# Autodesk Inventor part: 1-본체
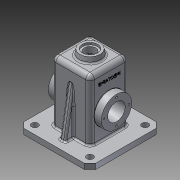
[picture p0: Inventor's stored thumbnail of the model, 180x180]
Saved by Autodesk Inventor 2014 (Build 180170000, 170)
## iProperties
Created: 2016-02
Part Number: 1-본체
Material: 알루미늄 6061
Document SubType Name: Modeling
Designer: J.H.CHAE
Density: 2.71 g/cm^3
Appearance: 알루미늄 - 평지
Mass: 933.088 g
Surface Area: 1044.63 cm^2
Volume: 344.313 cm^3
Author: J.H.CHAE
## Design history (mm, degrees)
sketch "스케치1"
  geometry: L1 (-65, -65)-(65, -65); L2 (65, -65)-(65, 65); L3 (65, 65)-(-65, 65); L4 (-65, 65)-(-65, -65); 1 further point
  constraints: 8 end point, 2 parallel, 1 horizontal, 1 perpendicular
  dimensions: "d0" = 130 distance of L3.end L1.start; "d1" = 130 distance of L1.start L1.end; "d2" = 65 distance from line of L3 point (0, 0) (= 0.5 x d0); "d3" = 65 distance from line of L4 point (0, 0) (= 0.5 x d1)
extrude "돌출1" new body sketch "스케치1" distance "d4" = 10; taper "d5" = 0 deg
sketch "스케치2"
  geometry: L1 (35, 120)-(-35, 120); L2 (-35, 120)-(-35, 10); L3 (-35, 10)-(35, 10); L4 (35, 10)-(35, 120); L5 (-65, 0)-(65, 0) reference; L6 (-65, 10)-(65, 10) reference; 2 further points
  constraints: 8 end point, 2 midpoint, 2 parallel, 1 horizontal, 1 perpendicular
  dimensions: "d6" = 120 distance between parallel lines of L5 L1; "d7" = 70 distance of L1.start L1.end
extrude "돌출2" join sketch "스케치2" stored distance "d8" = 70; taper "d9" = 0 deg
sketch "스케치7"
  geometry: L1 (10, -30)-(10, 100) reference; C1 r 27.5 at (-45, 35); 2 further points
  constraints: 1 centre point, 1 horizontal alignment, 1 midpoint
  dimensions: "d28" = 55 distance from line of L1 C1.centre; "d29" = 55 diameter of C1
extrude "돌출6" join sketch "스케치7" distance "d30" = 13; taper "d31" = 0 deg
sketch "스케치5"
  geometry: L1 (-65, 0)-(-65, 10) reference; L2 (-65, 10)-(-35, 10) reference; L3 (-35, 10)-(-35, 27.5) reference; L4 (-35, 82.5)-(-35, 120) reference; L5 (-35, 120)-(35, 120) reference; L6 (35, 120)-(35, 10) reference; L7 (35, 10)-(65, 10) reference; L8 (65, 10)-(65, 0) reference; L9 (65, 0)-(-65, 0) reference; L10 (-30, 0)-(-30, 115); L11 (-30, 115)-(30, 115); L12 (30, 115)-(30, 0); L13 (-35, 27.5)-(-48, 27.5) reference; L14 (-48, 27.5)-(-48, 82.5) reference; L15 (-48, 82.5)-(-35, 82.5) reference; 1 further point
  constraints: 6 end point, 2 point on line, 2 other
  dimensions: "d14" = 5 distance between parallel lines of L6 L12
extrude "돌출4" cut sketch "스케치5" stored distance "d15" = 60; taper "d16" = 0 deg
sketch "스케치6"
  geometry: C1 r 27.5 at (55, 30) reference; 1 further point
extrude "돌출5" join sketch "스케치6" distance "d17" = 7; taper "d18" = -45 deg
hole "구멍1" diameter "d21" = 32; stored, may be unused: countersink angle "d25" = 90 deg, drill point angle "d27" = 118 deg; dims "d22" = 6, "d23" = 4, "d24" = 2, "d26" = 8, "d32" = 10, "d33" = 10
sketch "스케치8"
  geometry: C1 r 20 at (35, -35); 1 further point
  constraints: 1 centre point, 1 coincident
  dimensions: "d34" = 40 diameter of C1
extrude "돌출7" join sketch "스케치8" distance "d35" = 10; taper "d36" = -10 deg
hole "구멍2" diameter "d39" = 21; stored, may be unused: countersink angle "d43" = 90 deg, drill point angle "d45" = 118 deg; dims "d37" = 10, "d38" = 10, "d40" = 6, "d41" = 28, "d42" = 4, "d44" = 8
sketch "스케치10"
  geometry: L1 (50, 10)-(35, 95.069); L2 (65, 10)-(-65, 10) reference; L3 (65, 0)-(65, 10) reference; L4 (35, 10)-(35, 120) reference; 1 further point
  constraints: 2 end point, 2 point on line
  dimensions: "d46" = 15 distance from line of L3 L1.start; "d47" = 10 deg angle of L1 L3
feature "리브1" sketch "스케치10" dims "d48" = 1, "d49" = 10, "d50" = 0, "d51" = 0, "d52" = 1, "d53" = 1
sketch "스케치11"
  geometry: C1 r 16 at (0, 0) reference; 2 further points
  constraints: 1 horizontal alignment
  dimensions: "d54" = 22.5 distance of C1.centre point (-22.5, 0)
hole "구멍3" sketch "스케치11" at (-22.5, 0) diameter "d55" = 3.242; stored, may be unused: countersink angle "d59" = 90 deg, drill point angle "d61" = 118 deg; dims "d56" = 8, "d57" = 28, "d58" = 4, "d60" = 10
fillet "모깎기1" dims "d65" = 8
fillet "모깎기2" dims "d66" = 8
fillet "모깎기3" dims "d67" = 3
fillet "모깎기4" dims "d68" = 3
fillet "모깎기5" dims "d69" = 3
fillet "모깎기6" dims "d70" = 3
fillet "모깎기7" dims "d71" = 3
fillet "모깎기8" dims "d72" = 3
fillet "모깎기9" dims "d73" = 3
chamfer "모따기1" distance "d74" = 10; stored, may be unused: second distance "d75" = 2, angle "d76" = 45 deg
sketch "스케치12"
  geometry: L1 (50, -50)-(-50, -50); L2 (-50, -50)-(-50, 50); L3 (-50, 50)-(50, 50); L4 (50, 50)-(50, -50); 3 further points
  constraints: 8 end point, 2 midpoint, 2 parallel, 1 horizontal, 1 horizontal alignment, 1 perpendicular, 1 vertical alignment
  dimensions: "d77" = 100 distance of L1.start L1.end; "d78" = 100 distance of L1.end L2.end
hole "구멍4" sketch "스케치12" at (50, -50), (-50, 50), (-50, -50), (50, 50) diameter "d79" = 12; stored, may be unused: countersink angle "d83" = 90 deg, drill point angle "d85" = 118 deg; dims "d80" = 8, "d81" = 28, "d82" = 4, "d84" = 10
fillet "모깎기10" dims "d86" = 0.5
fillet "모깎기11" dims "d87" = 3
fillet "모깎기12" dims "d88" = 0.5
sketch "스케치13"
  geometry: L1 (9.312, 4.061)-(9.312, 49.939); L2 (9.312, 49.939)-(14.688, 49.939); L3 (14.688, 49.939)-(14.688, 4.061); L4 (14.688, 4.061)-(9.312, 4.061); L5 (-18, 8.763)-(-18, 45.237) reference; L6 (99, 62)-(0, 62) reference; 3 further points
  constraints: 2 midpoint, 1 vertical, 2 other
  dimensions: "d89" = 30 distance from line of L5 point (12, 4.061); "d90" = 35 distance from line of L6 point (9.312, 27)
feature "엠보싱1" sketch "스케치13" dims "d0" = 130, "d1" = 130, "d2" = 65 (= 0.5 x d0), "d3" = 65 (= 0.5 x d1), "d91" = 0.5, "d92" = 0
node "솔리드1"
mirror "대칭1"
mirror "대칭2"
pattern_circular "원형 패턴1" dims angle "d63" = 360 deg
mirror "대칭3"
node "절단 모서리 투영1"
